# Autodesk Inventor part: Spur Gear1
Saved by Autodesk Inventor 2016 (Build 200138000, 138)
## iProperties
Created: 2015-03
Part Number: Spur Gear1
Material: Steel
Document SubType Name: Modeling
Designer: Uglješa
Categories: <?xml version="1.0" encoding="UTF-16"?> <MemberInstance><Categories><FamilyTemplate><FamilyTemplateParameter ValueType="xs:double" Id="1" ObjectReferenceKey="da
Density: 1 g/cm^3
Appearance: Steel
CustomPartVersion: 1
Author: Uglješa
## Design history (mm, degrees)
sketch "Sketch1"
  geometry: C1 r 56.77 at (0, 0)
  constraints: 1 centre point
  dimensions: "d0" = 113.5407 diameter of C1 (= da_da)
extrude "Extrusion1" new body sketch "Sketch1" distance "d1" = 30 (= da_b); taper "d2" = 0 deg
workplane "Work Plane2"
sketch "Sketch2"
  geometry: C1 r 56.77 at (0, 0) reference; C2 r 54.857 at (0, 0)
  constraints: 1 centre point, 1 coincident
  dimensions: "d3" = 109.71429 diameter of C2 (= da_dw)
feature "Pitch Diameter" sketch "Sketch2" dims "d4" = 10, "d5" = 0
workplane "Work Plane8"
workplane "Work Plane9"
feature "Spur Gear" dims "da_b" = 30, "da_d" = 109.06138, "da_aw" = 80, "da_da" = 113.5407, "da_df" = 103.43638, "da_dw" = 109.71429, angle "da_beta" = 8 deg, "da_lefttooth" = 10, "da_righttooth" = 0
node "Keyway3"
body "Solid1"
body "Srf1"
feature "Hub Keyway"
other parameters: "d17" = 0, "d34" = 0.6545 (computed from da_z), "d39" = 0, "d41" = 0, "d47" = 0, "d48" = 0
